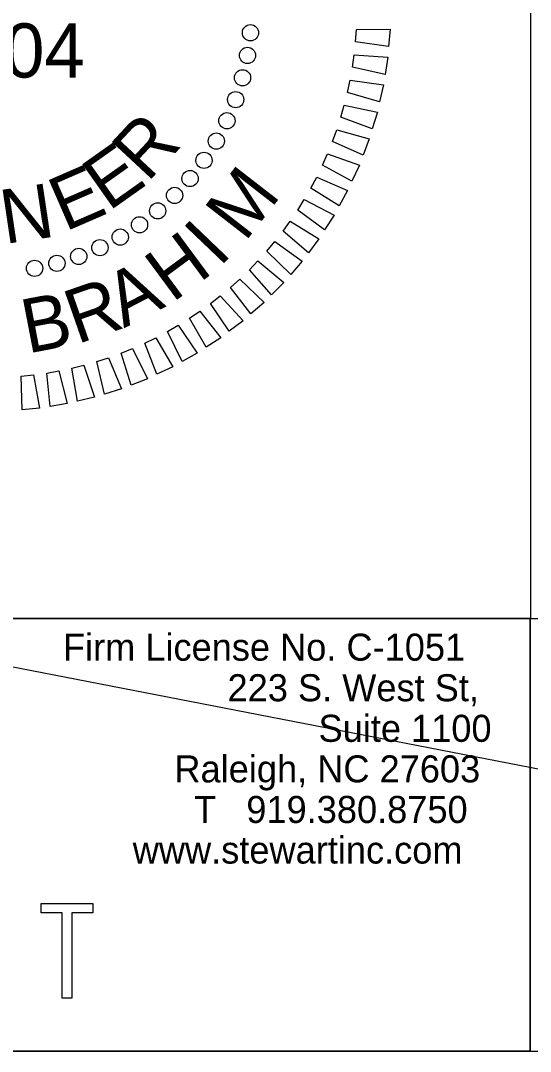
# Model space of a CAD drawing. Extents: x 1632447 to 1634147, y 883210 to 885181.
# Drawn here: x 1633966.7 to 1634013.8, y 884795.1 to 884890.3 of the extents above; entities that cross this region are included whole.
import ezdxf

# ---------------------------------------------------------------- set-up
doc = ezdxf.new("R2010")
doc.units = 0
for name, color, linetype in [('Default', 7, 'Continuous'), ('Scratch_Level_8', 7, 'Continuous'), ('Sheet PE Seal Cell', 7, 'Continuous'), ('Sheet Plan And Profile CELL', 7, 'Continuous'), ('Sheet Profile CELL', 7, 'Continuous')]:
    doc.layers.add(name, color=color, linetype=linetype)

msp = doc.modelspace()

# ---------------------------------------------------------------- linework, layer by layer
at = {"layer": 'Default'}
msp.add_line((1633913.826, 884795.058), (1634113.863, 884795.058), dxfattribs=at)
msp.add_line((1633913.826, 884795.058), (1634113.863, 884795.058), dxfattribs=at)
for points in [[(1633913.813, 884835.058), (1634013.813, 884835.058), (1634013.813, 884795.058), (1633913.813, 884795.058)], [(1634013.813, 884835.058), (1633913.813, 884835.058), (1633913.813, 884795.058), (1634013.813, 884795.058)]]:
    msp.add_lwpolyline(points, close=True, dxfattribs=at)
msp.add_lwpolyline([(1633968.637, 884807.866), (1633968.637, 884808.723), (1633973.427, 884808.723), (1633973.427, 884807.866), (1633971.478, 884807.866), (1633971.478, 884799.973), (1633970.586, 884799.973), (1633970.586, 884807.866), (1633968.637, 884807.866)], dxfattribs=at)
at = {"layer": 'Scratch_Level_8'}
msp.add_lwpolyline([(1632663.863, 883947.608), (1632663.863, 885084.125), (1634063.863, 884811.558), (1634013.863, 884541.527), (1634013.863, 883947.608)], close=True, dxfattribs=at)
at = {"layer": 'Sheet PE Seal Cell'}
for points in [[(1633997.769, 884889.506), (1634000.889, 884889.525), (1634000.748, 884887.915), (1633997.696, 884888.366)], [(1633997.56, 884887.142), (1634000.675, 884886.944), (1634000.421, 884885.348), (1633997.409, 884886.01)], [(1633997.187, 884884.799), (1634000.281, 884884.384), (1633999.916, 884882.809), (1633996.957, 884883.68)], [(1633996.652, 884882.488), (1633999.709, 884881.858), (1633999.235, 884880.313), (1633996.344, 884881.388)], [(1633995.957, 884880.22), (1633998.962, 884879.378), (1633998.382, 884877.869), (1633995.573, 884879.144)], [(1633995.105, 884878.005), (1633998.044, 884876.956), (1633997.361, 884875.491), (1633994.647, 884876.959)], [(1633994.101, 884875.856), (1633996.96, 884874.604), (1633996.176, 884873.191), (1633993.571, 884874.844)], [(1633992.949, 884873.782), (1633995.714, 884872.333), (1633994.833, 884870.978), (1633992.35, 884872.809)], [(1633991.656, 884871.793), (1633994.313, 884870.155), (1633993.339, 884868.865), (1633990.99, 884870.864)], [(1633990.227, 884869.899), (1633992.763, 884868.08), (1633991.702, 884866.861), (1633989.498, 884869.019)], [(1633988.669, 884868.109), (1633991.072, 884866.118), (1633989.929, 884864.976), (1633987.881, 884867.282)], [(1633986.99, 884866.433), (1633989.249, 884864.279), (1633988.028, 884863.219), (1633986.146, 884865.663)], [(1633985.199, 884864.878), (1633987.301, 884862.571), (1633986.01, 884861.599), (1633984.303, 884864.168)], [(1633983.303, 884863.451), (1633985.239, 884861.004), (1633983.883, 884860.124), (1633982.36, 884862.806)], [(1633981.312, 884862.16), (1633983.073, 884859.584), (1633981.659, 884858.801), (1633980.327, 884861.583)], [(1633979.236, 884861.011), (1633980.813, 884858.318), (1633979.348, 884857.636), (1633978.213, 884860.504)], [(1633977.086, 884860.01), (1633978.471, 884857.214), (1633976.962, 884856.635), (1633976.029, 884859.575)], [(1633974.87, 884859.162), (1633976.057, 884856.275), (1633974.511, 884855.803), (1633973.786, 884858.801)], [(1633970.289, 884857.937), (1633971.062, 884854.914), (1633969.466, 884854.662), (1633969.165, 884857.732)], [(1633972.601, 884858.469), (1633973.583, 884855.507), (1633972.008, 884855.144), (1633971.494, 884858.186)], [(1633967.945, 884857.568), (1633968.506, 884854.498), (1633966.896, 884854.358), (1633966.81, 884857.441)]]:
    msp.add_lwpolyline(points, close=True, dxfattribs=at)
for centre in [(1633987.983, 884889.194), (1633987.707, 884887.097), (1633987.249, 884885.032), (1633986.613, 884883.014), (1633985.804, 884881.059), (1633984.827, 884879.183), (1633983.69, 884877.399), (1633982.402, 884875.72), (1633980.973, 884874.161), (1633979.413, 884872.731), (1633977.735, 884871.444), (1633975.951, 884870.307), (1633972.12, 884868.52), (1633974.074, 884869.33), (1633970.102, 884867.884), (1633968.037, 884867.426)]:
    msp.add_circle(centre, 0.75, dxfattribs=at)
at = {"layer": 'Sheet Plan And Profile CELL'}
for p, q in [((1634013.838, 884947.558), (1634013.838, 884835.058)), ((1633913.826, 884795.058), (1634113.863, 884795.058))]:
    msp.add_line(p, q, dxfattribs=at)
at = {"layer": 'Sheet Profile CELL'}
msp.add_lwpolyline([(1633913.813, 884947.558), (1633913.813, 884835.058), (1634113.863, 884835.058)], dxfattribs=at)

# ---------------------------------------------------------------- texts
at = {"layer": 'Default'}
for s, p in [('Firm License No. C-1051', (1633970.657, 884831.16)), ('223 S. West St,', (1633985.864, 884827.41)), ('Suite 1100', (1633994.27, 884823.66)), ('Raleigh, NC 27603', (1633980.957, 884819.91)), ('T   919.380.8750', (1633982.77, 884816.16)), ('www.stewartinc.com', (1633977.108, 884812.41))]:
    msp.add_text(s, height=2.5, rotation=0, dxfattribs=at).set_placement(p)
at = {"layer": 'Sheet PE Seal Cell'}
for s, rotation, p in [('20204', 360, (1633954.078, 884885.058)), ('R', 47.04295, (1633978.46, 884875.291)), ('E', 35.28071, (1633974.887, 884872.644)), ('E', 23.51847, (1633970.85, 884870.781)), ('M', 52.18948, (1633987.465, 884869.779)), ('N', 8.46841, (1633965.279, 884869.661)), ('I', 46.24951, (1633985.111, 884867.448)), ('H', 36.49663, (1633980.761, 884864.187)), ('A', 27.44914, (1633976.286, 884861.861)), ('R', 19.24049, (1633971.954, 884860.384)), ('B', 10.89839, (1633967.381, 884859.532))]:
    msp.add_text(s, height=5, rotation=rotation, dxfattribs=at).set_placement(p)

doc.saveas('drawing.dxf')
